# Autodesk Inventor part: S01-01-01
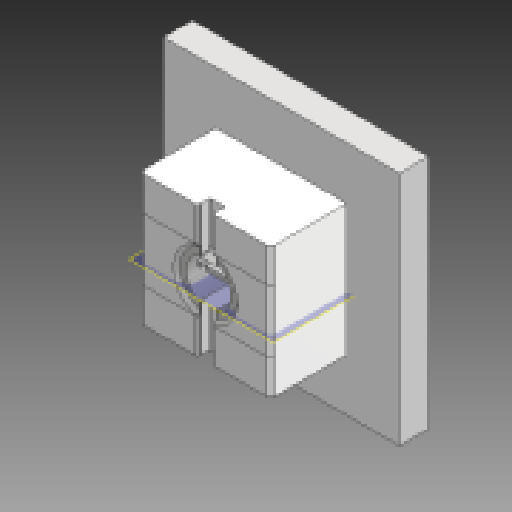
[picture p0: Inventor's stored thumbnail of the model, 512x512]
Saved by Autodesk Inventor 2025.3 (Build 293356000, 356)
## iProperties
Part Number: S01-01-01
Material: Generický
Document SubType Name: Modelování
Designer: Patrik
Appearance: Výchozí
Description: Tvárnice
Author: Patrik
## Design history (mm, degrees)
node "Sestava - mold design_MODEL - mk4 Blenddoor Tab v4_2_MP"
sketch "Náčrt2"
  geometry: L1 (45, 0)-(0, 0) reference; L2 (0, 0)-(0, -45) reference; L3 (0, -45)-(45, -45) reference; L4 (45, -45)-(45, 0) reference; L5 (-18, -63)-(-18, 18); L6 (-18, 18)-(63, 18); L7 (63, 18)-(63, -63); L8 (63, -63)-(-18, -63); 1 further point
  constraints: 8 end point, 3 other
  dimensions: "d3" = 18 distance between parallel lines of L2 L5
extrude "Vysunutí2" join sketch "Náčrt2" distance "d4" = 10; taper "d5" = 0 deg
feature "Vyřezání1"
node "Pracovní rovina2"
sketch "Náčrt3"
  geometry: L1 (-2.65, -37.706)-(-2.65, -15.041); L2 (-2.752, -15.94)-(-2.548, -15.94) reference; L3 (-17.95, -36.165)-(-17.95, -31.135) reference; L4 (-11.15, -23.935)-(-11.15, -22.435) reference; L5 (-13.5, -29.935)-(-13.5, -27.936) reference; L6 (-17.95, -31.135)-(-13.5, -27.936); L7 (-13.5, -27.936)-(-11.15, -23.935); L8 (-11.15, -22.435)-(-10.65, -21.935) reference; L9 (-10.65, -21.935)-(-6.966, -19.591); L10 (-6.966, -19.591)-(-2.752, -15.94); L11 (-17.95, -36.165)-(-2.65, -36.165); A1 r 1 centre (-6.429, -20.435) between (-6.429, -19.435) and (-7.414, -20.261) reference; 2 further points
  constraints: 12 end point, 1 perpendicular, 1 point on circle, 1 point on line, 1 tangent, 1 vertical
revolve "Rotace1" sketch "Náčrt3" stored, may be unused: angle "d9" = 360 deg
chamfer "Zkosení1" distance "d10" = 0.5; stored, may be unused: second distance "d11" = 1.25, angle "d12" = 45 deg
chamfer "Zkosení2" distance "d13" = 1.25; stored, may be unused: second distance "d14" = 1.25, angle "d15" = 45 deg
node "Objemová tělesa"
node "Povrchová tělesa"
feature "Těleso7::Sestava - mold design_MODEL - mk4 Blenddoor Tab v4_"
tag "Prvek štítků3"
node "Promítnutá smyčka1"
node "Těleso7"
feature "Sestava - mold design_MODEL - mk4 Blenddoor Tab v4_2_MP_Těle"
feature "Plocha1"
node "Povrch1"
other parameters: "d6" = -18.53
